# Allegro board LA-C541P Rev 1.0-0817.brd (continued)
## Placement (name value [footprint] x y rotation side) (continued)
PD704  SDMK0340L-7-F_SOD323-2~D  [SDMK0340L-7-F_SOD323-2]  34.78 37.29 90 top
PD1001  PDS5100H-13_POWERDI5-3~D  [PDS5100H-13_POWERDI5-3]  123.04 135.17 0 bottom
PD1002  PDS5100H-13_POWERDI5-3~D  [PDS5100H-13_POWERDI5-3]  291.05 14.73 270 top
PD1010  BAT54CW-7-F SOT-323  [BAT54CW_SOT323-3]  341.26 54.97 90 top
PD1100  -  [SDMK0340L-7-F_SOD323-2]  338.99 58.95 0 top
PD1101  SDMK0340L-7-F_SOD323-2~D  [SDMK0340L-7-F_SOD323-2]  266.42 40.29 90 bottom
PD1102  -  [SDMK0340L-7-F_SOD323-2]  323.83 46.95 270 top
PD1103  -  [SDMK0340L-7-F_SOD323-2]  322.13 46.95 270 top
PH1100  100K_0402_1%_TSM0B104F4251RZ  [R_0402]  225.96 69.49 0 bottom
PH1101  220K_0402_5%_ERTJ0EV224J  [R_0402]  234.12 67.33 180 bottom
PH1102  220K_0402_5%_ERTJ0EV224J  [R_0402]  221.26 17.23 0 top
PH1103  220K_0402_5%_ERTJ0EV224J  [R_0402]  242.06 66.97 180 bottom
PH1104  220K_0402_5%_ERTJ0EV224J  [R_0402]  235.86 17.8 180 top
PH1600  100K_0402_1%_TSM0B104F4251RZ  [R_0402]  259.64 18.83 0 top
PH1601  100K_0402_1%_TSM0B104F4251RZ  [R_0402]  261.81 22.58 90 top
PJP1  JUMP_1x3m  [JUMP_43X118]  45.47 33.61 90 top
PJP2  PAD-OPEN1x1m  [JUMP_43X39]  197.26 129.88 0 bottom
PJP3  -  [JUMP_43X79]  35.08 15.67 180 top
PJP4  PAD-OPEN1x1m  [JUMP_43X39]  34.62 18.74 180 top
PJP5  -  [JUMP_43X79]  31.65 16.78 180 top
PJP6  PAD-OPEN1x1m  [JUMP_43X39]  193.86 99.46 180 top
PJP7  PAD-OPEN1x3m  [JUMP_43X118]  196.32 99.56 0 top
PJP8  -  [JUMP_43X79]  121.34 102.84 270 bottom
PJP9  -  [JUMP_43X79]  14.79 41.7 0 top
PJP10  -  [JUMP_43X79]  221.67 126.31 270 top
PJP11  -  [JUMP_43X79]  224.29 118.36 180 top
PJP12  PAD-OPEN1x1m  [JUMP_43X39]  188.68 114.83 180 bottom
PJP13  PAD-OPEN1x1m  [JUMP_43X39]  192.59 102.92 90 bottom
PJP14  PAD-OPEN1x1m  [JUMP_43X39]  287.71 30.88 0 top
PJP15  -  [JUMP_43X79]  150.47 127.88 270 top
PJP16  -  [JUMP_43X79]  179.73 99.21 0 top
PJP17  PAD-OPEN 4x4m  [JUMP_43X118]  222.79 98.85 270 top
PJP18  PAD-OPEN 4x4m  [JUMP_43X118]  228.05 98.85 270 top
PJP19  -  [JUMP_43X79]  150.63 118.94 180 top
PJP20  -  [JUMP_43X79]  210.67 98.95 270 top
PJP21  -  [JUMP_43X79]  214.33 93.57 180 top
PJP22  PAD-OPEN 4x4m  [JUMP_43X118]  304.88 25.9 90 top
PJP23  -  [JUMP_43X79]  304.86 33.98 180 top
PJP24  -  [JUMP_43X79]  245.8 79.6 180 top
PJP25  -  [JUMP_43X79]  323.73 29 90 top
PJP26  -  [JUMP_43X79]  119.8 140 90 bottom
PJP100  PAD-OPEN 43x118  [JUMP_43X118]  342.35 5.59 270 top
PJP101  PAD-OPEN 43x118  [JUMP_43X118]  347.69 5.59 270 top
PJP102  PAD-OPEN 43x118  [JUMP_43X118]  346.1 49.25 90 bottom
PJP103  PAD-OPEN 43x118  [JUMP_43X118]  340.7 49.25 90 bottom
PJP200  PAD-OPEN 1x2m~D  [JUMP_43X79]  78.46 13.44 90 bottom
PJP201  PAD-OPEN1x1m  [JUMP_43X39]  64.68 15.7 180 bottom
PJP202  PAD-OPEN1x1m  [JUMP_43X39]  63.92 13.42 180 bottom
PJP203  JUMP_1x3m  [JUMP_43X118]  74.17 31.71 180 bottom
PJP204  JUMP_1x3m  [JUMP_43X118]  74.51 37.04 180 bottom
PJP300  PAD-OPEN 43x118  [JUMP_43X118]  317.95 17.61 180 top
PJP301  PAD-OPEN 1x2m~D  [JUMP_43X79]  334.14 17.48 180 top
PJP400  -  [JUMP_43X79]  12.42 56.68 0 top
PJP401  -  [JUMP_43X79]  22.87 61.21 90 top
PJP500  -  [JUMP_43X79]  81.68 10.33 0 top
PJP700  PAD-OPEN1x1m  [JUMP_43X39]  270.41 34.42 90 bottom
PJP800  PAD-OPEN 1x2m~D  [JUMP_43X79]  102.09 114.45 90 top
PJP801  PAD-OPEN 43x118  [JUMP_43X118]  101.32 114.57 270 bottom
PJP900  PAD-OPEN1x1m  [JUMP_43X39]  231.18 91.54 270 bottom
PJP901  PAD-OPEN1x1m  [JUMP_43X39]  232.37 81.77 270 bottom
PJP1100  PAD-OPEN1x1m  [JUMP_43X39]  260.07 47.9 180 bottom
PJP1800  -  [JUMP_43X79]  63.65 8.28 0 top
PJPDC1  ACES_50493-0110N-001  [ACES_50493-0110N-001_11P]  31.11 55.66 0 bottom
PL1  SMB3025500YA_2P  [CHENG_SMB3025500YA_2P]  236.15 78.7 180 top
PL2  FBMJ4516HS720NT_2P  [TAIYO_FBMJ4516HS720NT_2P]  266.6 7.96 180 top
PL3  BLM15BX102SN1D_2P  [MURAT_BLM15HG601SN1D_2P]  14.96 20.93 270 top
PL4  SMB3025500YA_2P  [CHENG_SMB3025500YA_2P]  46.11 50.11 180 bottom
PL5  SMB3025500YA_2P  [CHENG_SMB3025500YA_2P]  46.11 46.6 180 bottom
PL6  FBMJ4516HS720NT_2P  [TAIYO_FBMJ4516HS720NT_2P]  266.6 10.31 180 top
PL100  1UH_6.6A_20%_5X5X3_M  [L_5X5X3_M_2P]  338.19 14.28 90 top
PL101  2.2UH_7.8A_20%  [PANAS_ETQP3W2R2WFN_2P]  346.04 13.7 270 top
PL102  3.3UH_PIMB104T-3R3MS_10A_20%  [TOKO_FDVE1040-H-3R3M-P3_2P]  343.87 35.5 90 bottom
PL201  1UH_11A_20%_7X7X3_M  [L_7X7X3_M_2P]  69.96 26.67 270 top
PL301  1UH_6.6A_20%_5X5X3_M  [L_5X5X3_M_2P]  325.61 17.61 180 top
PL400  1UH_2.8A_30%_4X4X2_F  [L_4X4X2_F_2P]  21.38 55.71 90 top
PL500  HCB1608KF-121T30_0603  [TAI-T_HCB1608KF-121T3_L0603_2P]  68.06 10.61 0 top
PL501  1UH_1277AS-H-1R0N-P2_3.3A_30%  [MAG_MLV-FY12N1R0M-O1L_2P]  76.53 8.97 0 top
PL700  1UH_6.6A_20%_5X5X3_M  [L_5X5X3_M_2P]  296.4 15.78 270 top
PL701  3.3UH_6.5A_20%_7X7X3_M  [L_7X7X3_M_2P]  279.36 25.82 270 top
PL800  1UH_6.6A_20%_5X5X3_M  [L_5X5X3_M_2P]  95.74 124.78 270 bottom
PL1100  HCB2012KF-121T50_0805  [TAI-T_HCB2012KF-121T50_2P]  238.15 8.6 270 top
PL1101  HCB2012KF-121T50_0805  [TAI-T_HCB2012KF-121T50_2P]  239.86 8.59 270 top
PL1200  0.15UH_PCME064T-R15MS_36A_20%  [CYNTE_PCME064T-R15MS_4P]  234.59 62.89 180 bottom
PL1201  0.15UH_PCME064T-R15MS_36A_20%  [CYNTE_PCME064T-R15MS_4P]  234.59 52.73 180 bottom
PL1202  0.15UH_PCME064T-R15MS_36A_20%  [CYNTE_PCME064T-R15MS_4P]  234.59 42.57 180 bottom
PL1400  0.15UH_PCME064T-R15MS_36A_20%  [CYNTE_PCME064T-R15MS_4P]  228.63 12.97 180 top
PL1401  0.15UH_PCME064T-R15MS_36A_20%  [CYNTE_PCME064T-R15MS_4P]  228.63 23.13 180 top
PL1402  0.15UH_PCME064T-R15MS_36A_20%  [CYNTE_PCME064T-R15MS_4P]  228.63 33.29 180 top
PL1600  0.47UH_MMD05CZR47M_12A_20%  [MAG_MMD05CZR47M_4P]  255.76 22.7 270 top
PL1700  0.47UH_MMD05CZR47M_12A_20%  [MAG_MMD05CZR47M_4P]  228.21 73.02 180 bottom
PL1800  HCB1608KF-121T30_0603  [TAI-T_HCB1608KF-121T3_L0603_2P]  50.33 11.42 270 top
PL1801  1UH_1277AS-H-1R0N-P2_3.3A_30%  [MAG_MLV-FY12N1R0M-O1L_2P]  59.3 8.53 0 top
PQ1  AO3409_SOT23  [NTR4502PT1G_SOT23-3]  249.48 10.82 90 top
PQ2  FDV301N_G_NL_SOT23-3~D  [FDV301N_NL_SOT23-3]  12.68 23.47 90 top
PQ3  -  [MMST3904-7-F_SOT323-3]  11.14 28.01 270 top
PQ5  SI7149DP  [SI7447DP_SO8_5P]  38.84 50.95 270 bottom
PQ8  DCX124EK-7-F_SC74R-6  [IMD2AT-108_SC74-6]  14.95 25.29 180 top
PQ100  -  [SIS412DN-T1-GE3_POWERPAK8-5]  340.74 21.57 90 top
PQ101  -  [SIS412DN-T1-GE3_POWERPAK8-5]  347.85 39.94 180 top
PQ102  -  [FDMC7692S_MLP8-5]  344.49 25.27 180 top
PQ103  -  [FDMC7692S_MLP8-5]  349.76 38.31 0 top
PQ201  -  [SIR472DP-T1-GE3_POWERPAK8-5]  67.72 22.31 0 bottom
PQ202  SIRA06DP-T1_POWERPAK-SO8-5  [SIR472DP-T1-GE3_POWERPAK8-5]  74.77 27.83 270 bottom
PQ700  DMP3056L-7 1P SOT23-3  [NTR4502PT1G_SOT23-3]  40.35 34.72 0 bottom
PQ701  SI7149DP  [SI7447DP_SO8_5P]  41.96 38.12 180 bottom
PQ702  DMP3056L-7 1P SOT23-3  [NTR4502PT1G_SOT23-3]  44.35 34.72 0 bottom
PQ703  DMP3056L-7 1P SOT23-3  [NTR4502PT1G_SOT23-3]  35.98 29.05 180 bottom
PQ704  -  [SIR472DP-T1-GE3_POWERPAK8-5]  284.06 27.93 270 top
PQ705  -  [FDMC7692S_MLP8-5]  286.6 20.36 90 top
PQ706  DMP3056L-7 1P SOT23-3  [NTR4502PT1G_SOT23-3]  32 31.86 0 bottom
PQ707  -  [DMN66D0LDW-7_SOT363-6]  269.05 24.28 270 top
PQ708  -  [DMN65D8LDW-7_SOT363-6]  30.96 37.71 0 top
PQ800  -  [SIS412DN-T1-GE3_POWERPAK8-5]  99.78 120.82 270 top
PQ801  -  [SI7716ADN-T1-GE3_POWERPAK8-5]  96.12 118.31 0 top
PQ1001  SI7149DP  [SI7447DP_SO8_5P]  127.23 138.45 90 bottom
PQ1002  -  [SI4835DDY-T1-E3_SO8]  261.92 16.15 270 top
PQ1003  SI7149DP  [SI7447DP_SO8_5P]  259.87 13.48 180 top
PQ1004  SI7149DP  [SI7447DP_SO8_5P]  287.7 15.07 180 top
PQ1005  -  [DMN65D8LDW-7_SOT363-6]  269.79 39.69 90 bottom
PQ1011  SSM3K7002FU_SC70-3~D  [SSM3K7002FU_SC70-3]  342.12 61.11 90 top
PQ1072  AO3409_SOT23  [NTR4502PT1G_SOT23-3]  345.97 53.87 0 top
PQ1073  -  [DMN65D8LDW-7_SOT363-6]  27.73 37.1 90 top
PQ1074  -  [DMN65D8LDW-7_SOT363-6]  338.32 43.46 90 top
PR1  1K_0402_5%  [R_0402]  48.49 27.96 180 bottom
PR2  100K_0402_5%  [R_0402]  250.15 7.44 90 top
PR3  100_0804_8P4R_5%  [RP_0804_8P4R]  252.09 7.13 90 top
PR7  0_0402_5%  [R_0402]  12.55 20.93 180 top
PR8  2.2K_0402_5%  [R_0402]  9.75 19.98 0 top
PR9  33_0402_5%  [R_0402]  10.71 20.93 180 top
PR10  100K_0402_1%  [R_0402]  13.82 20.04 90 top
PR11  10K_0402_1%  [R_0402]  11.49 25.99 180 top
PR12  15K_0402_1%  [R_0402]  14.71 19.09 180 top
PR13  10K_0402_5%  [R_0402]  9.86 27.55 180 top
PR16  1M_0402_5%  [R_0402]  45.93 44.19 270 bottom
PR18  100K_0402_5%  [R_0402]  30.91 45.44 270 bottom
PR19  4.7K_0805_5%  [R_0805]  47.45 44.17 270 bottom
PR20  10K_0402_5%  [R_0402]  43.52 43.25 270 bottom
PR22  1M_0402_5%  [R_0402]  45.24 41.85 0 bottom
PR33  0_0402_5%  [R0402_0OHM]  249.21 13.29 180 top
PR100  6.49K_0402_1%  [R_0402]  345.83 30.44 0 top
PR101  15K_0402_1%  [R_0402]  348.59 33.29 0 bottom
PR102  10K_0402_1%  [R_0402]  349.54 31.07 180 bottom
PR103  0_0402_5%  [R0402_0OHM]  344.89 32.29 270 top
PR104  10K_0402_1%  [R_0402]  348.63 32.34 0 bottom
PR105  22.1K_0402_1%  [R_0402]  345.83 29.55 0 top
PR106  22.1K_0402_1%  [R_0402]  347.18 33.18 270 top
PR107  100K_0402_1%  [R_0402]  346.68 30.56 180 bottom
PR108  0_0402_5%  [R0402_0OHM]  345.77 31.45 0 bottom
PR109  2.2_0603_5%  [R_0603]  351.52 34.16 90 top
PR110  2.2_0603_5%  [R_0603]  352.13 26.56 90 top
PR111  4.7_1206_5%  [R_1206]  346.42 22.5 90 top
PR112  4.7_1206_5%  [R_1206]  353.66 41.17 270 top
PR113  0_0402_5%  [R_0402]  346.51 27.45 0 top
PR114  200_0402_1%  [R_0402]  350.83 33.29 270 bottom
PR200  2.2_0603_5%  [R_0603]  64.16 17.42 180 bottom
PR201  5.11K_0402_1%  [R_0402]  60.16 21.37 270 bottom
PR202  4.7_1206_5%  [R_1206]  66.7 18.88 180 top
PR203  5.1_0603_5%  [R_0603]  55.33 21.61 270 bottom
PR204  12K_0402_1%  [R_0402]  56.16 16.1 270 top
PR205  1M_0402_1%  [R_0402]  55.45 17.93 0 bottom
PR206  200K_0402_5%  [R_0402]  55.45 17.04 0 bottom
PR207  20K_0402_1%  [R_0402]  57.67 16.97 0 top
PR208  100K_0402_5%  [R_0402]  55.45 16.15 0 bottom
PR209  100K_0402_1%  [R_0402]  55.4 19.2 0 bottom
PR210  2.2_0603_5%  [R_0603]  59.21 22.18 180 bottom
PR303  1M_0402_1%  [R_0402]  328.35 21.61 180 top
PR305  4.7_1206_5%  [R_1206]  324 13.55 0 top
PR306  0_0402_5%  [R_0402]  329.91 21.62 270 top
PR307  36.5K_0402_1%  [R_0402]  332.05 23.58 0 top
PR308  0_0402_5%  [R0402_0OHM]  331.04 21.61 0 top
PR309  1K_0402_5%  [R_0402]  332.97 22.69 180 top
PR310  62K_0402_1%  [R_0402]  331.18 22.68 90 top
PR311  10_0402_1%  [R_0402]  333.86 24.53 180 top
PR312  0_0603_5%  [R_0603]  325.15 22.5 270 top
PR314  0_0402_5%  [R0402_0OHM]  332.08 24.53 180 top
PR315  100K_0402_1%  [R_0402]  330.11 22.5 180 top
PR316  0_0402_5%  [R0402_0OHM]  332.08 25.42 180 top
PR400  100K_0402_5%  [R_0402]  13.19 60.35 0 top
PR401  0_0402_5%  [R0402_0OHM]  18.21 59.47 180 top
PR402  1M_0402_5%  [R_0402]  18.21 58.58 180 top
PR403  4.7_0603_5%  [R_0603]  18.17 53.56 180 top
PR404  36.5K_0402_1%  [R_0402]  15.96 60.43 180 top
PR405  11.5K_0402_1%  [R_0402]  15.05 58.66 0 top
PR500  100K_0402_1%  [R_0402]  76.13 5.46 270 top
PR501  0_0402_5%  [R_0402]  77.06 5.47 270 top
PR502  100K_0402_5%  [R_0402]  77.33 6.9 180 top
PR503  2.2_0603_5%  [R_0603]  74.54 12.03 90 top
PR504  4.7_1206_5%  [R_1206]  77.47 11.38 90 top
PR505  100_0402_1%  [R_0402]  70.34 12.94 270 top
PR506  0_0402_5%  [R_0402]  71.26 12.95 270 top
PR507  0_0402_5%  [R_0402]  75.19 5.47 270 top
PR508  0_0402_5%  [R_0402]  72.22 12.93 270 top
PR509  100K_0402_1%  [R_0402]  69.38 12.04 90 top
PR510  1M_0402_1%  [R_0402]  74.29 5.48 270 top
PR511  10K_0402_1%  [R_0402]  70.53 5.49 270 top
PR512  10K_0402_1%  [R_0402]  72.43 4.6 90 top
PR513  10K_0402_1%  [R_0402]  69.59 4.57 90 top
PR514  10K_0402_1%  [R_0402]  71.49 5.5 270 top
PR700  0_0402_5%  [R_0402]  335.11 49.12 270 top
PR701  0.005_1206_1%  [R_1206_4P-D]  43.52 40.15 0 bottom
PR703  0_0402_5%  [R_0402]  37.55 33.01 180 bottom
PR704  100_0402_1%  [R_0402]  42.71 30.75 180 bottom
PR706  4.12K_0603_1%  [R_0603]  275.75 37.97 270 top
PR709  100K_0402_1%  [R_0402]  35.81 27.26 180 bottom
PR710  0_0402_5%  [R0402_0OHM]  41.81 29.5 270 bottom
PR711  0_0402_5%  [R0402_0OHM]  42.7 29.5 270 bottom
PR712  100K_0402_1%  [R_0402]  34.03 27.26 180 bottom
PR713  12.1_0402_1%  [R_0402]  33.56 33.93 0 bottom
PR714  0_0402_5%  [R0402_0OHM]  31.34 27.26 0 bottom
PR715  20_0402_1%  [R_0402]  34.47 32.91 180 bottom
PR716  0_0402_5%  [R0402_0OHM]  269.92 38.39 270 top
PR717  10_1206_5%  [R_1206]  282.39 41.98 180 top
PR718  49.9K_0402_1%  [R_0402]  272.58 37.6 90 top
PR719  294K_0402_1%  [R_0402]  272.6 36.72 180 top
PR720  121K_0402_1%  [R_0402]  274.73 37.43 180 top
PR721  0_0402_5%  [R0402_0OHM]  274.73 36.54 180 top
PR722  100K_0402_1%  [R_0402]  273.81 38.31 0 top
PR723  0.01_1206_1%  [R_1206_4P-D]  274.75 18.37 180 top
PR724  4.7_1206_5%  [R_1206]  283.93 18.28 0 top
PR725  0_0402_5%  [R_0402]  268.49 33.42 0 top
PR726  0_0402_5%  [R0402_0OHM]  268.49 35.2 0 top
PR727  0_0402_5%  [R0402_0OHM]  268.49 32.53 0 top
PR728  0_0402_5%  [R0402_0OHM]  270.92 28.07 90 top
PR729  0_0402_5%  [R0402_0OHM]  268.49 31.64 0 top
PR730  0_0402_5%  [R_0402]  268.49 34.31 0 top
PR737  665K_0402_1%  [R_0402]  267.6 30.75 0 top
PR738  3M_0402_5%  [R_0402]  269.39 30.77 270 top
PR740  10K_0402_1%  [R_0402]  269.46 28.9 270 top
PR743  0_0402_5%  [R0402_0OHM]  268.52 27.2 180 top
PR744  45.3K_0402_1%  [R_0402]  267.61 34.27 180 top
PR745  100K_0402_1%  [R_0402]  268.52 28.98 180 top
PR757  10K_0402_5%  [R_0402]  271.81 28.99 270 top
PR758  20K_0402_1%  [R_0402]  270.21 25.3 180 top
PR760  5.36K_0402_1%  [R_0402]  271.04 25.3 0 top
PR761  10_0402_1%  [R_0402]  275.12 27.12 90 top
PR762  10_0402_1%  [R_0402]  274.17 27.12 90 top
PR764  2.74K_0402_1%  [R_0402]  271.91 24.45 270 top
PR765  2.2_0603_5%  [R_0603]  277.28 32.75 0 top
PR766  0_0402_5%  [R_0402]  32.49 36.66 0 top
PR767  1M_0402_5%  [R_0402]  31.54 36.66 180 top
PR768  1M_0402_5%  [R_0402]  33.38 39.71 270 top
PR769  1M_0402_5%  [R_0402]  31.67 40.6 180 top
PR770  1M_0402_5%  [R_0402]  29.57 38.56 270 top
PR771  0_0402_5%  [R_0402]  26.78 39.64 0 top
PR772  100K_0402_1%  [R_0402]  26.78 40.6 0 top
PR773  0_0402_5%  [R_0402]  24.93 40.6 0 top
PR800  100K_0402_5%  [R_0402]  102.24 130.6 90 top
PR801  2.2_0603_5%  [R_0603]  103.74 125.05 270 top
PR802  107K_0402_1%  [R_0402]  102.98 128.59 180 bottom
PR804  0_0402_5%  [R_0402]  99.01 129.42 0 bottom
PR805  4.7_1206_5%  [R_1206]  93.96 121.1 270 top
PR806  470K_0402_1%  [R_0402]  98.47 129.84 90 top
PR807  5.11K_0402_1%  [R_0402]  99.44 130.48 90 top
PR808  12K_0402_1%  [R_0402]  100.37 129.84 90 top
PR809  0_0402_5%  [R_0402]  99.01 128.54 0 bottom
PR900  0_0402_5%  [R0402_0OHM]  236.82 91.23 270 bottom
PR901  47K_0402_5%  [R_0402]  234.92 90.34 90 bottom
PR902  12.7K_0402_1%  [R_0402]  234.09 82.02 0 bottom
PR903  10K_0402_1%  [R_0402]  235.93 82.04 0 bottom
PR1001  330K_0402_5%  [R_0402]  326.73 53.56 270 top
PR1002  0_0402_5%  [R_0402]  126.62 143.63 180 bottom
PR1003  330K_0402_5%  [R_0402]  282.46 5.02 0 top
PR1004  0_0402_5%  [R0402_0OHM]  251.94 14.43 180 top
PR1005  1K_1206_5%  [R_1206]  282.73 6.54 0 top
PR1006  0_0402_5%  [R0402_0OHM]  328.24 54.44 0 top
PR1007  100_0603_1%  [R_0603]  327.69 53.36 0 top
PR1008  100_0603_1%  [R_0603]  327.69 55.96 0 top
PR1009  0_0402_5%  [R0402_0OHM]  336.45 59.34 270 top
PR1010  100_0603_1%  [R_0603]  327.69 52.15 0 top
PR1011  47_0805_5%  [R_0805]  326.97 49.42 0 top
PR1012  0_0402_5%  [R0402_0OHM]  330.67 58.43 90 top
PR1013  100K_0402_5%  [R_0402]  332.96 46.38 90 top
PR1014  0_0402_5%  [R0402_0OHM]  332.45 58.43 90 top
PR1015  100_0603_1%  [R_0603]  334.04 47.65 90 top
PR1016  0_0402_5%  [R0402_0OHM]  331.56 58.43 90 top
PR1017  0_0402_5%  [R0402_0OHM]  332.96 48.2 90 top
PR1018  1M_0402_5%  [R_0402]  334.21 60.22 0 top
PR1019  0_0402_5%  [R0402_0OHM]  333.34 58.43 90 top
PR1020  0_0402_5%  [R0402_0OHM]  334.23 58.43 90 top
PR1021  0_0402_5%  [R0402_0OHM]  336 48.2 90 top
PR1022  0_0402_5%  [R0402_0OHM]  336.89 48.2 90 top
PR1023  0_0402_5%  [R0402_0OHM]  335.11 58.43 90 top
PR1024  0_0402_5%  [R0402_0OHM]  337.34 58.43 90 top
PR1025  0_0402_5%  [R0402_0OHM]  338.34 57.17 0 top
PR1026  100_0603_1%  [R_0603]  326 50.92 0 top
PR1027  0_0402_5%  [R0402_0OHM]  338.34 55.39 0 top
PR1028  1M_0402_5%  [R_0402]  338.34 56.28 0 top
PR1029  100_0603_1%  [R_0603]  338.42 54 0 top
PR1030  10K_0402_5%  [R_0402]  341.86 57.61 180 top
PR1031  330K_0402_5%  [R_0402]  342.1 53.22 180 top
PR1032  0_0402_5%  [R0402_0OHM]  341.77 56.73 0 top
PR1033  0_0402_5%  [R_0402]  268.84 41.22 90 bottom
PR1034  1M_0402_5%  [R_0402]  270.63 42.12 180 bottom
PR1035  1M_0402_5%  [R_0402]  270.5 38.37 180 bottom
PR1036  1M_0402_5%  [R_0402]  271.64 37.23 180 bottom
PR1037  1M_0402_5%  [R_0402]  269.87 37.23 180 bottom
PR1099  100K_0402_5%  [R_0402]  347.49 57.65 180 top
PR1100  100_0402_1%  [R_0402]  201.48 55.84 180 top
PR1101  12K_0402_1%  [R_0402]  265.32 44.86 90 top
PR1102  7.5K_0603_1%  [R_0603]  264.19 46.33 270 top
PR1103  499_0402_1%  [R_0402]  265.21 39.83 180 top
PR1104  45.3_0402_1%  [R_0402]  265.21 42.69 180 top
PR1105  100_0402_1%  [R_0402]  264.3 40.79 0 top
PR1106  0_0402_5%  [R0402_0OHM]  261.52 54.42 0 top
PR1107  0_0402_5%  [R0402_0OHM]  264.19 52.1 270 top
PR1108  0_0402_5%  [R0402_0OHM]  261.52 53.53 0 top
PR1109  1K_0402_1%  [R_0402]  263.3 52.1 270 top
PR1110  100_0402_1%  [R_0402]  262.14 39.83 0 top
PR1111  100_0402_1%  [R_0402]  201.48 56.79 180 top
PR1112  30K_0402_1%  [R_0402]  259.47 46.31 0 bottom
PR1113  10_0402_1%  [R_0402]  262.14 40.79 0 top
PR1114  10K_0402_1%  [R_0402]  263.12 44.66 180 top
PR1115  0_0402_5%  [R0402_0OHM]  263.05 41.74 180 top
PR1116  14.3K_0402_1%  [R_0402]  263.12 48.22 180 top
PR1117  49.9_0402_1%  [R_0402]  262.14 42.69 0 top
PR1118  1.5K_0402_1%  [R_0402]  264.52 49.99 180 top
PR1119  100_0402_1%  [R_0402]  217.86 42.37 180 bottom
PR1120  34.8K_0402_1%  [R_0402]  260.39 44.53 180 bottom
PR1121  0_0402_5%  [R0402_0OHM]  259.22 51.33 0 bottom
PR1122  0_0402_5%  [R0402_0OHM]  258.28 53.16 90 bottom
PR1123  1K_0402_1%  [R_0402]  259.22 54.06 0 bottom
PR1124  100_0402_1%  [R_0402]  200.56 44.41 0 top
PR1125  100_0402_1%  [R_0402]  217.86 43.33 180 bottom
PR1126  0_0402_5%  [R0402_0OHM]  261.58 37.63 270 top
PR1127  1K_0402_1%  [R_0402]  260.69 39.4 270 top
PR1128  0_0402_5%  [R0402_0OHM]  259.79 36.72 0 top
PR1129  100_0402_1%  [R_0402]  200.56 45.36 0 top
PR1130  49.9_0402_1%  [R_0402]  259.74 51.25 90 top
PR1131  1K_0402_1%  [R_0402]  259.73 50.38 0 top
PR1132  25.5K_0402_1%  [R_0402]  257.07 48.01 90 bottom
PR1133  3.65K_0402_1%  [R_0402]  257.96 50.36 90 top
PR1134  49.9_0402_1%  [R_0402]  258.91 38.51 270 top
PR1135  24.9K_0402_1%  [R_0402]  258.72 41.47 90 bottom
PR1136  1K_0402_1%  [R_0402]  258.01 39.39 0 top
PR1137  3.65K_0402_1%  [R_0402]  258.04 35.83 180 top
PR1138  12.7K_0402_1%  [R_0402]  257.07 51.28 270 top
PR1139  16.2K_0402_1%  [R_0402]  256.26 38.5 180 top
PR1140  75K_0402_1%  [R_0402]  257.09 53.04 180 top
PR1141  75K_0402_1%  [R_0402]  255.35 37.61 0 top
PR1142  165K_0402_1%  [R_0402]  256.2 52.15 180 top
PR1143  93.1K_0402_1%  [R_0402]  250.54 53.17 90 top
PR1144  165K_0402_1%  [R_0402]  256.26 35.83 180 top
PR1145  107K_0402_1%  [R_0402]  252.58 36.09 180 top
PR1146  93.1K_0402_1%  [R_0402]  251.44 53.18 90 top
PR1147  107K_0402_1%  [R_0402]  252.58 37.1 180 top
PR1148  93.1K_0402_1%  [R_0402]  252.87 53.72 0 top
PR1149  107K_0402_1%  [R_0402]  252.58 38.12 180 top
PR1150  1K_0402_1%  [R_0402]  250.46 47.26 0 top
PR1151  2.2_0603_5%  [R_0603]  249.9 46.18 0 top
PR1152  75K_0402_1%  [R_0402]  254.27 43.01 0 bottom
PR1153  24.9K_0402_1%  [R_0402]  254.27 42.12 0 bottom
PR1154  2.26K_0402_1%  [R_0402]  252.37 51.28 270 bottom
PR1155  52.3K_0402_1%  [R_0402]  254.27 47.45 0 bottom
PR1156  3.92K_0402_1%  [R_0402]  254.27 46.57 0 bottom
PR1157  24.9K_0402_1%  [R_0402]  254.27 45.68 0 bottom
PR1158  97.6K_0402_1%  [R_0402]  254.27 44.79 0 bottom
PR1159  97.6K_0402_1%  [R_0402]  254.27 43.9 0 bottom
PR1160  2.26K_0402_1%  [R_0402]  252.13 41.55 180 bottom
PR1161  2.26K_0402_1%  [R_0402]  253.26 51.28 270 bottom
PR1162  2.26K_0402_1%  [R_0402]  252.13 40.53 180 bottom
PR1163  2.26K_0402_1%  [R_0402]  254.15 51.28 270 bottom
PR1164  2.26K_0402_1%  [R_0402]  252.13 39.52 180 bottom
PR1165  0_0402_5%  [R0402_0OHM]  251.37 48.15 180 top
PR1166  0_0402_5%  [R0402_0OHM]  251.24 42.69 180 bottom
PR1167  61.9K_0402_1%  [R_0402]  249.59 48.15 180 top
PR1168  61.9K_0402_1%  [R_0402]  251.24 43.64 180 bottom
PR1169  1K_0402_1%  [R_0402]  251.49 51.28 270 top
PR1170  1K_0402_1%  [R_0402]  250.32 42.44 0 top
PR1198  0_0402_5%  [R0402_0OHM]  262.14 43.64 0 top
PR1199  45.3_0402_1%  [R_0402]  265.21 41.74 180 top
PR1200  2_0603_5%  [R_0603]  234.53 58.4 0 bottom
PR1201  2_0603_5%  [R_0603]  244.39 60.03 180 bottom
PR1202  2_0603_5%  [R_0603]  244.26 49.87 180 bottom
PR1203  2_0603_5%  [R_0603]  234.58 48.24 0 bottom
PR1204  10_0402_1%  [R_0402]  229.12 67.14 0 bottom
PR1205  10_0402_1%  [R_0402]  229.12 56.98 0 bottom
PR1206  2_1206_5%  [R_1206]  236.72 67.36 0 bottom
PR1207  2_1206_5%  [R_1206]  237.13 57.12 0 bottom
PR1208  2_0603_5%  [R_0603]  244.31 39.43 180 bottom
PR1209  2_0603_5%  [R_0603]  235.9 36.79 90 bottom
PR1210  10_0402_1%  [R_0402]  229.12 46.82 0 bottom
PR1211  2_1206_5%  [R_1206]  236.73 46.65 0 bottom
PR1400  2_0603_5%  [R_0603]  228.56 17.43 0 top
PR1401  2_0603_5%  [R_0603]  238.42 15.83 180 top
PR1402  2_0603_5%  [R_0603]  238.39 26.25 180 top
PR1403  2_0603_5%  [R_0603]  228.56 27.64 0 top
PR1404  10_0402_1%  [R_0402]  223.11 17.23 0 top
PR1405  10_0402_1%  [R_0402]  223.15 27.39 0 top
PR1406  2_1206_5%  [R_1206]  230.66 8.33 0 top
PR1407  2_1206_5%  [R_1206]  230.69 19.04 0 top
PR1408  2_0603_5%  [R_0603]  238.37 36.15 180 top
PR1409  2_0603_5%  [R_0603]  228.59 37.8 0 top
PR1410  10_0402_1%  [R_0402]  223.15 37.55 0 top
PR1411  2_1206_5%  [R_1206]  230.59 29.23 0 top
PR1600  27K_0402_1%  [R_0402]  261.8 30.2 180 top
PR1601  8.25K_0402_1%  [R_0402]  264.07 28.26 90 top
PR1602  15K_0402_1%  [R_0402]  261.4 28.33 90 top
PR1603  2_0603_5%  [R_0603]  261.93 33.56 270 top
PR1604  6.19K_0402_1%  [R_0402]  264.98 27.72 0 top
PR1605  1.5K_0402_1%  [R_0402]  264.4 25.01 0 top
PR1606  10K_0402_1%  [R_0402]  259.9 24 180 top
PR1607  100_0402_1%  [R_0402]  259.61 32.14 90 top
PR1608  10_0402_1%  [R_0402]  258.72 33.05 270 top
PR1609  0_0402_5%  [R_0402]  257.84 33.05 270 top
PR1610  150K_0402_1%  [R_0402]  261.14 26.12 0 top
PR1611  49.9_0402_1%  [R_0402]  256.95 33.05 270 top
PR1612  10K_0402_1%  [R_0402]  260.03 22.93 270 top
PR1613  0_0402_5%  [R_0402]  262.04 24.34 180 top
PR1614  2_1206_5%  [R_1206]  250.53 22.75 90 top
PR1615  2_0603_5%  [R_0603]  255.65 32.04 90 top
PR1616  61.9K_0402_1%  [R_0402]  260.92 23.47 270 top
PR1617  1K_0402_1%  [R_0402]  263.84 23.53 180 top
PR1618  866_0402_1%  [R_0402]  263.78 21.75 180 top
PR1619  866_0402_1%  [R_0402]  263.78 20.86 180 top
PR1620  100_0402_1%  [R_0402]  203.59 43.23 0 top
PR1621  100_0402_1%  [R_0402]  203.2 44.44 0 top
PR1700  2_0603_5%  [R_0603]  228.24 68.24 0 bottom
PR1701  2_0603_5%  [R_0603]  238.02 69.74 180 bottom
PR1702  2_1206_5%  [R_1206]  229.26 78.32 0 bottom
PR1800  100K_0402_1%  [R_0402]  59.29 5.3 270 top
PR1801  0_0402_5%  [R_0402]  60.24 5.3 270 top
PR1802  100K_0402_5%  [R_0402]  60.12 6.51 180 top
PR1803  2.2_0603_5%  [R_0603]  56.81 11.77 90 top
PR1804  4.7_1206_5%  [R_1206]  59.69 10.75 90 top
PR1805  100_0402_1%  [R_0402]  52.47 12.69 270 top
PR1806  0_0402_5%  [R_0402]  53.46 12.56 270 top
PR1807  0_0402_5%  [R_0402]  56.43 5.3 270 top
PR1808  0_0402_5%  [R_0402]  54.5 12.59 270 top
PR1809  1M_0402_1%  [R_0402]  57.38 5.3 270 top
PR1810  100K_0402_1%  [R_0402]  51.45 12.69 270 top
PR1811  10K_0402_1%  [R_0402]  53.57 5.3 270 top
PR1812  10K_0402_1%  [R_0402]  54.53 4.39 90 top
PR1813  10K_0402_1%  [R_0402]  52.62 4.39 90 top
PR1814  10K_0402_1%  [R_0402]  55.48 5.3 270 top
PR1815  0_0402_5%  [R_0402]  51.67 5.3 270 top
PT1  PAD~D  [TPC12]  201.4 106.7 0 top
PU1  -  [TS5A63157DCKR_SC70-6]  9.97 18.63 270 top
PU101  -  [TPS51285BRUKR_QFN20_3X3]  349.19 31.94 270 top
PU105  TC7SH08FU_SSOP5~D  [TC7SH08FU_SSOP5]  336.96 40.06 0 top
PU200  -  [RT8207MZQW_WQFN20_3X3]  60.58 15.87 180 bottom
PU300  -  [SYX198DQNC_QFN10_3X3]  328.66 19.02 0 top
PU400  -  [SY8003DFC_DFN8_2X2]  15.61 56.73 270 top
PU500  -  [NB681GD-Z_QFN13_2X3]  73.07 9.19 0 top
PU700  BQ24780S  [BQ24780RUYR_WQFN28_4X4]  274.28 34.71 270 top
PU800  -  [TPS51212DSCR_SON10_3X3]  101.84 128.29 180 top
PU900  -  [AP7175SP-13_SO-8EP-8]  236.5 83.55 180 bottom
PU1001  CD3301BRHHR  [CD3301RHHR_QFN36_6X6]  331.7 50.79 0 top
PU1100  -  [NCP81205MNTXG_QFN52_6X6]  259.35 48.24 270 top
PU1200  -  [NCP81382MNTXG_QFN39_4X6]  240.47 59.4 90 bottom
PU1201  -  [NCP81382MNTXG_QFN39_4X6]  240.47 49.11 90 bottom
PU1202  -  [NCP81382MNTXG_QFN39_4X6]  240.52 38.7 90 bottom
PU1400  -  [NCP81382MNTXG_QFN39_4X6]  234.5 16.46 270 top
PU1401  -  [NCP81382MNTXG_QFN39_4X6]  234.5 27 270 top
PU1402  -  [NCP81382MNTXG_QFN39_4X6]  234.48 37.19 270 top
PU1600  NCP81210MNTWG_QFN40_5x5  [NCP81210MNTWG_QFN40_5X5]  258.82 30.51 270 top
PU1700  -  [NCP81382MNTXG_QFN39_4X6]  234.13 68.99 90 bottom
PU1800  -  [NB681GD-Z_QFN13_2X3]  55.95 9.03 0 top
PWRSW1  @SHORT PADS~D  [SHORTPADS]  209.08 152.61 90 bottom
Q4  -  [DMN65D8LW-7_SOT323-3]  164.04 67.2 180 top
Q5  -  [DMN65D8LW-7_SOT323-3]  201.38 78.37 90 bottom
Q14  -  [MMBT3904WT1G_SC70-3]  107.67 34.63 90 top
Q15  -  [MMBT3904WT1G_SC70-3]  332.53 22.82 180 bottom
Q16  -  [MMBT3904WT1G_SC70-3]  179.34 44.37 90 bottom
Q17  -  [MMBT3904WT1G_SC70-3]  29.49 25.11 270 bottom
Q21  -  [DMP3050LVT-7_TSOT26-6]  110.29 138.55 270 bottom
Q22  -  [DMN65D8LW-7_SOT323-3]  111.93 134.26 270 bottom
Q24  -  [LP2301ALT1G_SOT23-3]  100.49 133.19 0 bottom
Q26  -  [MMBT3904WT1G_SC70-3]  241.32 69.63 270 bottom
Q27  -  [MMBT3904WT1G_SC70-3]  210.47 102.3 0 top
Q28  -  [MMBT3904WT1G_SC70-3]  198.61 99.23 90 bottom
Q29  -  [DMN66D0LDW-7_SOT363-6]  9.38 43.04 270 top
Q74  -  [DMN66D0LDW-7_SOT363-6]  304.19 8.1 270 top
Q86  -  [DDTA114EUA-7-F_SOT323-3]  308.88 7.51 90 top
Q87  -  [DMN65D8LW-7_SOT323-3]  226.8 110.7 180 top
Q186  -  [AO4435L_SO8]  230.21 106.55 180 top
Q295  -  [DMN66D0LDW-7_SOT363-6]  210.86 75.2 180 top
Q325  -  [DMN66D0LDW-7_SOT363-6]  240.35 117.52 0 top
Q327  -  [DMN65D8LW-7_SOT323-3]  229.91 124.23 270 top
Q343  -  [DMN66D0LDW-7_SOT363-6]  167.24 138.97 270 bottom
Q347  -  [DMN66D0LDW-7_SOT363-6]  171 132.67 180 bottom
Q353  -  [DMN66D0LDW-7_SOT363-6]  152.57 123.99 270 bottom
Q355  -  [DMN66D0LDW-7_SOT363-6]  149.58 114.08 0 bottom
Q359  -  [DMN65D8LW-7_SOT323-3]  302.67 11.92 0 top
Q364  -  [DMN66D0LDW-7_SOT363-6]  146.52 120.1 0 bottom
Q365  -  [DMN66D0LDW-7_SOT363-6]  170.02 141.88 0 bottom
Q366  -  [DMN66D0LDW-7_SOT363-6]  243.11 103.15 0 top
Q367  -  [DMN66D0LDW-7_SOT363-6]  168.87 95.53 0 top
Q369  -  [DMN66D0LDW-7_SOT363-6]  171.41 95.53 0 top
Q370  -  [DMN65D8LW-7_SOT323-3]  195.2 98.41 315 bottom
QE2  -  [DMN66D0LDW-7_SOT363-6]  213.51 104.28 90 bottom
QH3  -  [DMN65D8LW-7_SOT323-3]  111.93 131.66 270 bottom
QH4  -  [DMN66D0LDW-7_SOT363-6]  109.17 128.62 180 top
QH5  -  [DMN65D8LW-7_SOT323-3]  112.7 130.12 0 top
QN5  -  [DMN65D8LW-7_SOT323-3]  20.28 26.82 270 top
QV1  -  [DMN65D8LW-7_SOT323-3]  157.65 138.45 270 bottom
QZ2  -  [LP2301ALT1G_SOT23-3]  194.69 124.19 0 top
R1  4.7K_0402_5%  [R_0402]  210.37 72.16 180 top
R2  4.7K_0402_5%  [R_0402]  211.92 74.36 90 top
R3  4.3K_0402_5%  [R_0402]  165.76 76.73 0 top
R4  10K_0402_5%  [R_0402]  208.43 76.58 90 top
R5  4.3K_0402_5%  [R_0402]  165.76 77.62 0 top
R7  0_0402_5%  [R0402_0OHM]  170.58 126.72 0 bottom
R8  33_0402_5%  [R_0402]  170.58 125.76 0 bottom
R9  33_0402_5%  [R_0402]  170.58 124.81 0 bottom
R10  10K_0402_5%  [R_0402]  162.04 65.88 90 top
R11  10K_0402_5%  [R_0402]  174.81 69.93 180 top
R12  0_0402_5%  [R_0402]  238.89 86.96 90 top
R13  0_0402_5%  [R_0402]  240.25 93.39 270 top
R19  0_0402_5%  [R_0402]  174.08 76.35 0 top
R21  0_0402_5%  [R_0402]  257.56 93.87 90 top
R22  0_0402_5%  [R_0402]  257.55 88.29 180 top
R23  0_0402_5%  [R_0402]  240.77 95.16 270 top
R24  0_0402_5%  [R_0402]  240.97 91.59 180 top
R25  0_0402_5%  [R_0402]  256.66 91.94 0 top
R26  0_0402_5%  [R_0402]  256.65 93.87 90 top
R27  0_0402_5%  [R_0402]  257.55 90.2 180 top
R28  0_0402_5%  [R_0402]  257.55 89.3 180 top
R29  0_0402_5%  [R_0402]  239.68 92.29 0 bottom
R30  0_0402_5%  [R_0402]  239.74 93.37 0 bottom
R37  100K_0402_5%  [R_0402]  214.1 75.95 90 top
R38  0_0402_5%  [R_0402]  242.02 102.13 90 top
R39  0_0402_5%  [R_0402]  246.49 104.24 90 top
R40  0_0402_5%  [R_0402]  241.15 102.89 90 top
R41  0_0402_5%  [R_0402]  245.77 103.04 0 top
R42  100K_0402_5%  [R_0402]  119.36 142.95 90 bottom
R43  0_0402_5%  [R_0402]  193.15 112.51 180 bottom
R51  100K_0402_5%  [R_0402]  175.23 74.55 0 top
R60  100K_0402_5%  [R_0402]  144.09 77.49 0 top
R63  0_0603_5%  [R0603_0OHM]  229.89 110.16 90 top
R64  0_0603_5%  [R0603_0OHM]  231.29 110.16 90 top
R65  0_0603_5%  [R0603_0OHM]  232.06 112.52 90 top
R66  0_0603_5%  [R0603_0OHM]  233.44 112.52 90 top
R67  0_0603_5%  [R0603_0OHM]  234.07 110.11 90 top
R68  0_0603_5%  [R0603_0OHM]  235.46 110.11 90 top
R69  0_0603_5%  [R0603_0OHM]  236.31 112.49 90 top
R70  0_0603_5%  [R0603_0OHM]  237.71 112.49 90 top
R71  10K_0402_5%  [R_0402]  163.36 68.42 270 bottom
R72  0_0402_5%  [R0402_0OHM]  164.27 66.63 180 bottom
R96  4.99K_0402_1%  [R_0402]  174.82 138.07 90 top
R97  4.99K_0402_1%  [R_0402]  148.55 95.94 180 top
R98  4.7K_0402_5%  [R_0402]  177.5 138.97 180 top
R99  4.7K_0402_5%  [R_0402]  184.46 137.39 0 bottom
R100  4.7K_0402_5%  [R_0402]  145.98 142 180 top
R101  4.99K_0402_1%  [R_0402]  143.3 141.09 90 top
R102  4.7K_0402_5%  [R_0402]  148.52 97.75 180 top
R103  4.7K_0402_5%  [R_0402]  118.83 147.57 0 bottom
R104  4.7K_0402_5%  [R_0402]  148.26 108.67 180 top
R105  4.7K_0402_5%  [R_0402]  169.06 91.97 0 top
R106  4.99K_0402_1%  [R_0402]  171.74 92.87 270 top
R107  4.7K_0402_5%  [R_0402]  162.1 93.52 180 bottom
R109  4.7K_0402_5%  [R_0402]  155.35 136.16 0 bottom
R115  4.7K_0402_5%  [R_0402]  177.5 138.08 180 top
R116  4.7K_0402_5%  [R_0402]  185.03 137.98 270 top
R117  4.7K_0402_5%  [R_0402]  184.46 134.53 0 bottom
R118  4.7K_0402_5%  [R_0402]  184.46 135.48 0 bottom
R119  4.7K_0402_5%  [R_0402]  184.46 138.34 0 bottom
R120  4.7K_0402_5%  [R_0402]  184.43 140.6 0 bottom
R121  4.7K_0402_5%  [R_0402]  186.02 138.87 0 top
R122  4.7K_0402_5%  [R_0402]  184.5 140.29 0 top
R123  4.7K_0402_5%  [R_0402]  185.03 136.22 270 top
R124  4.7K_0402_5%  [R_0402]  184.46 136.43 0 bottom
R125  4.7K_0402_5%  [R_0402]  147.32 105.67 90 top
R126  4.7K_0402_5%  [R_0402]  146.44 105.67 90 top
R127  4.7K_0402_5%  [R_0402]  155.35 138.2 0 bottom
R128  4.7K_0402_5%  [R_0402]  149.39 97.76 270 top
R129  4.7K_0402_5%  [R_0402]  168.21 137.07 0 bottom
R130  560_0402_1%  [R_0402]  311.18 8.35 270 top
R131  560_0402_1%  [R_0402]  310.22 8.35 270 top
R132  4.7K_0402_5%  [R_0402]  168.21 136.18 0 bottom
R133  4.7K_0402_5%  [R_0402]  155.35 139.21 0 bottom
R134  4.7K_0402_5%  [R_0402]  208.88 108.66 180 bottom
R135  100K_0402_5%  [R_0402]  163.36 65.76 270 bottom
R136  4.7K_0402_5%  [R_0402]  145.98 141.11 180 top
R137  4.7K_0402_5%  [R_0402]  153.87 140.95 180 top
R138  4.7K_0402_5%  [R_0402]  153.87 141.91 180 top
R139  4.7K_0402_5%  [R_0402]  153.87 139.05 180 top
R140  4.7K_0402_5%  [R_0402]  155.35 133.12 0 bottom
R141  4.7K_0402_5%  [R_0402]  153.87 140 180 top
R142  4.7K_0402_5%  [R_0402]  155.35 134.13 0 bottom
R143  4.7K_0402_5%  [R_0402]  155.35 135.15 0 bottom
R146  4.7K_0402_5%  [R_0402]  148.21 105.67 90 top
R147  4.7K_0402_5%  [R_0402]  144.61 105.89 90 top
R148  4.7K_0402_5%  [R_0402]  150.88 105.67 90 top
R149  4.7K_0402_5%  [R_0402]  153.55 105.67 90 top
R150  4.7K_0402_5%  [R_0402]  149.99 106.37 180 top
R151  4.7K_0402_5%  [R_0402]  152.66 106.43 90 top
R152  4.7K_0402_5%  [R_0402]  151.77 105.67 90 top
R153  4.7K_0402_5%  [R_0402]  162.1 92.57 180 bottom
R154  4.7K_0402_5%  [R_0402]  162.1 91.61 180 bottom
R155  4.7K_0402_5%  [R_0402]  169.06 92.86 0 top
R156  4.7K_0402_5%  [R_0402]  162.1 92.61 180 top
R157  4.7K_0402_5%  [R_0402]  162.1 91.65 180 top
R158  4.7K_0402_5%  [R_0402]  162.1 94.51 180 top
R159  4.7K_0402_5%  [R_0402]  162.1 96.42 180 bottom
R160  4.7K_0402_5%  [R_0402]  162.1 93.56 180 top
R161  4.7K_0402_5%  [R_0402]  162.1 95.46 180 bottom
R162  4.7K_0402_5%  [R_0402]  162.1 94.47 180 bottom
R208  0_0603_5%  [R0603_0OHM]  110.76 150.47 0 bottom
R209  0_0603_1%  [R0603_0OHM]  254.36 116.16 90 top
R213  0_0603_5%  [R_0603]  269.4 41.69 135 top
R222  100K_0402_5%  [R_0402]  120.81 146.65 180 bottom
R317  20K_0402_5%  [R_0402]  9.17 53.12 0 top
R336  100K_0402_5%  [R_0402]  112.79 156.53 180 bottom
R339  100K_0402_5%  [R_0402]  112.79 155.64 180 bottom
R360  0_0402_5%  [R_0402]  25.43 11.58 90 top
R361  0_0402_5%  [R_0402]  239.65 90.67 0 top
R362  0_0402_5%  [R_0402]  252.65 85.31 270 top
R363  10K_0402_5%  [R_0402]  20.01 28.6 0 top
R370  33_0402_5%  [R_0402]  290.05 33.37 270 top
R371  560_0402_5%  [R_0402]  254.99 85.31 270 top
R372  0_0402_5%  [R0402_0OHM]  19.15 28.6 180 top
R373  2.2K_0402_5%  [R_0402]  250.82 85.48 0 top
R374  43K_0402_1%  [R_0402]  127.23 128.79 45 top
R375  1K_0402_5%  [R_0402]  248.17 83.71 270 top
R376  20K_0402_5%  [R_0402]  249.07 84.59 180 top
R377  1M_0402_5%  [R_0402]  240.86 120.5 0 top
R378  1M_0402_5%  [R_0402]  226.8 122.5 90 top
R379  10K_0402_5%  [R_0402]  180.05 118.26 0 bottom
R381  100K_0402_5%  [R_0402]  97.64 92.21 90 top
R382  10K_0402_5%  [R_0402]  142.12 133.56 180 top
R383  10K_0402_5%  [R_0402]  299.43 5.4 0 top
R384  10K_0402_5%  [R_0402]  299.5 4.31 0 top
R385  10K_0402_5%  [R_0402]  303.75 4.63 90 top
R386  0_0402_5%  [R_0402]  9.92 36.35 90 top
R387  10K_0402_5%  [R_0402]  298.75 6.67 180 top
R388  0_0402_5%  [R0402_0OHM]  49 31.19 0 top
R389  0_0402_5%  [R_0402]  299.08 8.15 90 top
R396  8.2K_0402_5%  [R_0402]  200.64 97.52 180 bottom
R399  2.2K_0402_5%  [R_0402]  202.99 98.75 90 bottom
R400  33_0402_5%  [R_0402]  290.05 34.23 90 top
R403  10K_0402_5%  [R_0402]  270.55 41.48 45 top
R405  10K_0402_5%  [R_0402]  237.06 87.83 0 top
R407  10K_0402_5%  [R_0402]  256.63 87.33 0 top
R408  10K_0402_5%  [R_0402]  237.06 88.74 0 top
R409  10K_0402_5%  [R_0402]  256.62 92.98 0 top
R410  10K_0402_5%  [R_0402]  257.52 96.59 180 top
R411  10K_0402_5%  [R_0402]  257.52 97.48 180 top
R413  10K_0402_5%  [R_0402]  239.7 89.78 0 top
R414  10K_0402_5%  [R_0402]  249.93 82.68 0 top
R415  100K_0402_5%  [R_0402]  335.2 42.9 270 bottom
R416  100K_0402_5%  [R_0402]  335.2 41.12 270 bottom
R417  0_0402_5%  [R_0402]  190.73 106.81 90 bottom
R418  0_0402_5%  [R_0402]  128.95 127.9 90 top
R422  100K_0402_5%  [R_0402]  107.46 133.35 0 bottom
R423  47K_0402_5%  [R_0402]  109.24 133.35 0 bottom
R425  1.33K_0402_1%  [R_0402]  207.88 99.16 270 bottom
R426  100K_0402_5%  [R_0402]  142.14 134.45 180 top
R427  0_0402_5%  [R_0402]  104.06 132.98 90 bottom
R428  0_0402_5%  [R_0402]  103.04 132.98 90 bottom
R429  0_0402_5%  [R_0402]  116.95 140.3 270 bottom
R430  0_0402_5%  [R_0402]  116.06 140.3 270 bottom
R432  47K_0402_5%  [R_0402]  208.9 113.19 180 bottom
R435  0_0402_5%  [R_0402]  197.39 97.68 0 bottom
R492  1M_0402_5%  [R_0402]  159.2 147.6 180 top
R501  10K_0402_5%  [R_0402]  4.75 48.98 180 top
R502  10K_0402_5%  [R_0402]  5.68 48.98 0 top
R503  100K_0402_5%  [R_0402]  9.31 44.27 90 top
R504  100K_0402_5%  [R_0402]  5.43 41.06 0 top
R506  100K_0402_5%  [R_0402]  10.22 40.66 180 top
R513  100K_0402_5%  [R_0402]  10.44 44.15 0 top
R519  100K_0402_5%  [R_0402]  157.15 76.86 180 top
R545  10K_0402_5%  [R_0402]  252.53 103.9 90 top
R546  10K_0402_5%  [R_0402]  253.99 103.9 90 top
R549  10K_0402_5%  [R_0402]  257.1 116.61 180 top
R553  4.7K_0402_5%  [R_0402]  255.83 120.8 180 top
R554  4.7K_0402_5%  [R_0402]  256.98 113.44 180 top
R555  0_0402_5%  [R0402_0OHM]  257.1 118.38 180 top
R556  0_0402_5%  [R0402_0OHM]  256.85 114.38 180 top
R557  10K_0402_5%  [R_0402]  256.19 117.5 0 top
R558  0_0402_5%  [R0402_0OHM]  254.92 119.91 0 top
R559  4.7K_0402_5%  [R_0402]  255.93 115.4 0 top
R561  1K_0402_1%  [R_0402]  251.07 104.81 270 top
R562  3.01K_0402_1%  [R_0402]  245.8 115.34 180 top
R571  75_0402_1%  [R_0402]  250.17 138.44 90 top
R572  75_0402_1%  [R_0402]  242.55 138.44 90 top
R573  75_0402_1%  [R_0402]  248.9 138.44 90 top
R574  75_0402_1%  [R_0402]  241.34 138.44 90 top
R720  100K_0402_5%  [R_0402]  321.72 34.82 270 top
R721  100K_0402_5%  [R_0402]  167.73 133.05 0 bottom
R722  100K_0402_5%  [R_0402]  167.73 134.01 0 bottom
R723  100K_0402_5%  [R_0402]  217.89 122.59 270 top
R755  10K_0402_5%  [R_0402]  190.99 143.91 0 bottom
R756  33_0402_5%  [R_0402]  188.69 147.53 90 top
R757  100K_0402_5%  [R_0402]  166.52 148.43 270 top
R758  100K_0402_5%  [R_0402]  147.65 77.49 0 top
R759  10K_0402_5%  [R_0402]  180.29 115.3 180 top
R763  10K_0402_5%  [R_0402]  170.65 106.89 0 bottom
R773  10K_0402_5%  [R_0402]  181.25 106.18 180 top
R775  10K_0402_5%  [R_0402]  176.66 105.21 90 top
R779  10K_0402_5%  [R_0402]  182.13 106.09 270 top
R782  100K_0402_5%  [R_0402]  171.57 107.78 180 bottom
R783  100K_0402_5%  [R_0402]  187.62 112.29 0 top
R795  10_0402_1%  [R_0402]  186.14 106.85 180 top
R797  0_0402_5%  [R0402_0OHM]  210.34 115.06 270 bottom
R800  100K_0402_5%  [R_0402]  170.65 111.28 0 bottom
R802  0_0402_5%  [R0402_0OHM]  192.24 106.67 0 bottom
R803  100K_0402_5%  [R_0402]  171.57 110.4 180 bottom
R804  1K_0402_1%  [R_0402]  182.9 115.28 90 top
R805  100K_0402_5%  [R_0402]  174.82 105.64 90 top
R807  10_0402_1%  [R_0402]  173.91 107.45 90 top
R810  100K_0402_5%  [R_0402]  208.88 119.51 270 bottom
R811  10K_0402_5%  [R_0402]  209.77 119.51 270 bottom
R814  100K_0402_5%  [R_0402]  192.11 111.27 0 bottom
R817  100K_0402_5%  [R_0402]  205.92 103.91 180 top
R819  100K_0402_5%  [R_0402]  208.9 120.38 180 bottom
R820  0_0402_5%  [R_0402]  216.06 123.47 0 top
R822  2.2K_0402_5%  [R_0402]  192.23 115.17 0 bottom
R825  10K_0402_5%  [R_0402]  207.98 121.27 0 bottom
R829  2.2K_0402_5%  [R_0402]  192.23 114.29 0 bottom
R834  0_0402_5%  [R0402_0OHM]  203.16 102.58 90 bottom
R835  10K_0402_5%  [R_0402]  196.31 123.25 270 bottom
R836  100_0402_1%  [R_0402]  191.79 119.56 0 bottom
R837  10K_0402_5%  [R_0402]  208.9 112.3 180 bottom
R838  2.2K_0402_5%  [R_0402]  208.9 114.16 180 bottom
R840  0_0402_5%  [R0402_0OHM]  216.06 122.58 0 top
R841  2.2K_0402_5%  [R_0402]  208.9 115.05 180 bottom
R843  8.2K_0402_5%  [R_0402]  192.18 109.43 0 bottom
R845  0_0402_5%  [R0402_0OHM]  198.27 118.67 0 bottom
R847  10K_0402_5%  [R_0402]  181.63 93.82 90 bottom
R848  10K_0402_5%  [R_0402]  179.85 93.82 90 bottom
R849  10K_0402_5%  [R_0402]  178.96 93.82 90 bottom
R850  100K_0402_5%  [R_0402]  180.74 93.82 90 bottom
R858  10K_0402_5%  [R_0402]  187.02 92.36 90 bottom
R859  10K_0402_5%  [R_0402]  184.99 92.3 90 bottom
R860  10K_0402_5%  [R_0402]  184.1 92.3 90 bottom
R861  10K_0402_5%  [R_0402]  182.52 93.82 90 bottom
R862  0_0402_5%  [R_0402]  177.37 102.46 180 bottom
R863  0_0402_5%  [R_0402]  177.37 101.57 180 bottom
R864  49.9_0402_1%  [R_0402]  187.91 92.36 90 bottom
R866  0_0402_5%  [R0402_0OHM]  196.5 118.65 90 bottom
R869  10K_0402_5%  [R_0402]  187.86 116.99 90 top
R870  100K_0402_5%  [R_0402]  206.19 119.35 90 bottom
R872  10K_0402_5%  [R_0402]  204.12 123.63 270 bottom
R874  1K_0402_5%  [R_0402]  200.88 122.72 90 bottom
R875  62K_0402_5%  [R_0402]  208.9 111.42 180 bottom
R876  100K_0402_5%  [R_0402]  201.77 122.72 90 bottom
R877  0_0402_5%  [R_0402]  154.87 122.19 180 top
R878  0_0402_5%  [R0402_0OHM]  154.79 125.25 270 top
R879  10K_0402_5%  [R_0402]  203.23 123.63 270 bottom
R880  100K_0402_5%  [R_0402]  207.08 119.35 90 bottom
R881  0_0402_5%  [R0402_0OHM]  307.93 30.5 180 top
R885  10_0402_1%  [R_0402]  197.14 103.76 270 bottom
R892  10K_0402_5%  [R_0402]  192.23 113.4 0 bottom
R895  33_0402_5%  [R_0402]  179.28 125.95 0 bottom
R897  33_0402_5%  [R_0402]  187.42 120.67 0 bottom
R899  33_0402_5%  [R_0402]  176.69 118.89 0 bottom
R900  33_0402_5%  [R_0402]  187.42 119.65 0 bottom
R901  33_0402_5%  [R_0402]  178.54 119.86 270 bottom
R932  10K_0402_5%  [R_0402]  300.25 7.25 90 top
R935  100K_0402_5%  [R_0402]  219.43 91.33 180 top
R936  0_0402_5%  [R_0402]  179.28 126.91 0 bottom
R940  100K_0402_5%  [R_0402]  225.07 103.83 90 top
R943  1K_0402_5%  [R_0402]  308.52 5.8 180 top
R944  20K_0402_5%  [R_0402]  225.08 106.57 180 top
R953  33_0402_5%  [R_0402]  194.49 118.65 90 bottom
R955  1K_0402_5%  [R_0402]  304.44 10.57 270 top
R956  430_0402_5%  [R_0402]  300.89 11.06 90 top
R1068  0_0402_5%  [R0402_0OHM]  203.61 118.59 90 bottom
R1069  1K_0402_5%  [R_0402]  198.01 103.74 0 bottom
R1137  10K_0402_5%  [R_0402]  110.83 151.53 90 bottom
R1138  100K_0402_5%  [R_0402]  111.74 151.52 90 bottom
R1144  0_0402_5%  [R0402_0OHM]  251.34 115.18 180 top
R1167  150_0402_5%  [R_0402]  250.8 144.48 180 top
R1170  150_0402_5%  [R_0402]  250.8 145.37 180 top
R1171  150_0402_5%  [R_0402]  228.69 146.44 90 top
R1970  0_0402_5%  [R0402_0OHM]  209.28 90.64 270 top
R1971  0_0402_5%  [R0402_0OHM]  208.39 90.64 270 top
R1972  0_0402_5%  [R0402_0OHM]  213.22 76.86 180 top
R1977  10K_0402_5%  [R_0402]  209.38 76.58 90 top
R1978  10K_0402_5%  [R_0402]  163.49 76.46 90 bottom
R1981  100K_0402_5%  [R_0402]  192.7 120.45 180 bottom
R1985  0_0402_5%  [R0402_0OHM]  207.99 119.51 270 bottom
R2158  100K_0402_5%  [R_0402]  187.82 106.26 180 bottom
R2160  100K_0402_5%  [R_0402]  167.73 155.46 90 top
R2164  33_0402_5%  [R_0402]  157.11 145.5 0 top
R2165  33_0402_5%  [R_0402]  157.11 144.61 0 top
R2166  33_0402_5%  [R_0402]  160.93 147.52 90 top
R2167  33_0402_5%  [R_0402]  161.82 147.52 90 top
R2168  33_0402_5%  [R_0402]  162.71 147.52 90 top
R2169  33_0402_5%  [R_0402]  163.6 147.52 90 top
R2170  33_0402_5%  [R_0402]  164.49 147.52 90 top
R2171  33_0402_5%  [R_0402]  165.38 147.52 90 top
R2172  33_0402_5%  [R_0402]  159.28 156.37 270 top
R2173  33_0402_5%  [R_0402]  160.17 156.37 270 top
R2174  33_0402_5%  [R_0402]  161.06 156.37 270 top
R2175  33_0402_5%  [R_0402]  161.95 156.37 270 top
R2176  33_0402_5%  [R_0402]  162.84 156.37 270 top
R2177  33_0402_5%  [R_0402]  163.73 156.37 270 top
R2178  33_0402_5%  [R_0402]  164.68 153.83 270 top
R2179  33_0402_5%  [R_0402]  165.57 153.83 270 top
R2189  100K_0402_5%  [R_0402]  146.52 122.7 0 bottom
R2194  4.7K_0402_5%  [R_0402]  150.26 110.76 180 bottom
R2195  4.7K_0402_5%  [R_0402]  168.75 139.78 0 top
R2196  4.7K_0402_5%  [R_0402]  170.91 142.32 0 top
R2197  100K_0402_5%  [R_0402]  148.77 122.6 0 bottom
R2198  4.7K_0402_5%  [R_0402]  149.76 115.53 0 bottom
R3664  1K_0402_5%  [R_0402]  170.58 123.86 0 bottom
R3665  1K_0402_5%  [R_0402]  179.28 124.05 0 bottom
R3666  1K_0402_5%  [R_0402]  179.28 123.1 0 bottom
R3667  33_0402_5%  [R_0402]  179.28 125 0 bottom
R3668  1K_0402_5%  [R_0402]  170.58 122.91 0 bottom
R3669  33_0402_5%  [R_0402]  171.49 121.95 180 bottom
R3670  33_0402_5%  [R_0402]  180.19 122.14 180 bottom
R3722  1M_0402_5%  [R_0402]  151.36 143.76 90 top
R3727  100K_0402_5%  [R_0402]  125.25 145.51 270 bottom
R3728  1K_0402_5%  [R_0402]  201.39 144.13 270 bottom
R3730  100K_0402_5%  [R_0402]  210.34 113.21 270 bottom
R3736  4.7K_0402_5%  [R_0402]  149.81 121.31 270 bottom
R3737  4.7K_0402_5%  [R_0402]  145.98 115.36 90 bottom
R3738  4.7K_0402_5%  [R_0402]  246.69 102.13 180 top
R3739  4.7K_0402_5%  [R_0402]  244.21 102.13 180 top
R3740  100K_0402_5%  [R_0402]  171.57 112.24 180 bottom
R3741  100K_0402_5%  [R_0402]  173.77 110.38 0 top
R3744  100K_0402_5%  [R_0402]  170.92 99.59 180 top
R3745  4.7K_0402_5%  [R_0402]  172.19 94.3 0 top
R3746  100K_0402_5%  [R_0402]  169.96 100.48 0 top
R3747  4.7K_0402_5%  [R_0402]  172.65 98.39 0 top
R3748  10K_0402_5%  [R_0402]  170.84 104.99 0 bottom
R3750  100K_0402_5%  [R_0402]  172.11 76.09 0 top
R3752  33_0402_5%  [R_0402]  293.93 41.54 270 top
R3753  100K_0402_5%  [R_0402]  35.89 22.65 270 top
R3754  33K_0402_5%  [R_0402]  205.91 109.89 90 top
R3755  33_0402_5%  [R_0402]  187.42 121.62 0 bottom
R3757  10_0402_1%  [R_0402]  206.66 132.35 0 bottom
R3758  33_0402_5%  [R_0402]  294.87 41.54 270 top
RC1  24.9_0402_1%  [R_0402]  203.18 66.01 270 top
RC2  24.9_0402_1%  [R_0402]  167.1 62.44 0 top
RC5  2.2K_0402_5%  [R_0402]  152.25 17.17 180 top
RC6  2.2K_0402_5%  [R_0402]  160.5 13.99 180 top
RC66  20_0402_5%  [R_0402]  189.65 71.32 90 bottom
RC74  10K_0402_5%  [R_0402]  120.77 130.67 270 top
RC75  10K_0402_5%  [R_0402]  105.61 115.8 180 top
RC76  10K_0402_5%  [R_0402]  105.61 116.69 180 top
RC79  10K_0402_5%  [R_0402]  112.5 120.8 0 bottom
RC121  1K_0402_5%  [R_0402]  145.96 13.79 90 top
RC122  0_0402_5%  [R_0402]  146.89 13.79 90 top
RC124  1K_0402_5%  [R_0402]  155.98 14.96 270 top
RC126  1K_0402_5%  [R_0402]  152.04 13.8 90 top
RC127  1K_0402_5%  [R_0402]  164.32 13.79 90 top
RC128  0_0402_5%  [R_0402]  160.57 125.13 270 top
RC129  0_0402_5%  [R_0402]  151.35 19.59 270 top
RC132  150_0402_5%  [R_0402]  161.52 14.29 90 top
RC133  1.5K_0402_5%  [R_0402]  159.68 125.13 270 top
RC135  51_0402_5%  [R_0402]  169.71 6.69 180 top
RC138  51_0402_5%  [R_0402]  147.8 13.79 90 top
RC143  0_0402_5%  [R_0402]  163.43 13.79 90 top
RC144  0_0402_5%  [R_0402]  160.5 14.94 180 top
RC154  0_0402_5%  [R0402_0OHM]  191.7 102.36 180 top
RC155  56.2_0402_1%  [R_0402]  195.64 5.53 0 top
RC156  220_0402_5%  [R_0402]  197.39 5.53 0 top
RC157  100_0402_5%  [R_0402]  195.64 6.45 0 top
RC158  499_0402_1%  [R_0402]  195.52 9.65 90 top
RC159  60.4_0402_1%  [R_0402]  156.81 68.04 270 top
RC164  1K_0402_5%  [R_0402]  157.75 68.04 270 top
RC166  1K_0402_5%  [R_0402]  163.43 15.56 90 top
RC167  30_0402_5%  [R_0402]  197.56 9.65 90 top
RC168  20_0402_5%  [R_0402]  196.67 9.65 90 top
RC169  0_0402_5%  [R0402_0OHM]  214.58 73.38 270 top
RC171  0_0402_5%  [R_0402]  165.75 23.38 270 top
RC172  49.9_0402_1%  [R_0402]  198 16.41 270 top
RC173  100_0603_1%~D  [R_0603]  187.05 32.34 90 bottom
RC174  100_0603_1%  [R_0603]  183.65 14.87 90 top
RC175  100_0603_1%  [R_0603]  181.17 14.87 90 top
RC176  100_0603_1%  [R_0603]  183.65 13.41 270 top
RC177  30_0402_5%  [R_0402]  197.84 80.23 270 bottom
RC178  0_0402_5%  [R_0402]  189.51 69.09 90 bottom
RC179  0_0402_5%  [R_0402]  190.4 69.09 90 bottom
RC180  1K_0402_5%  [R_0402]  194.64 10.57 270 top
RC181  1K_0402_5%  [R_0402]  145.97 16.54 270 top
RC216  0_0603_1%  [R0603_0OHM]  153.5 17.29 270 top
RC217  0_0402_5%  [R_0402]  161.52 12.52 90 top
RC220  0_0402_5%  [R0402_0OHM]  179.24 51.95 90 bottom
RC221  49.9_0402_1%  [R_0402]  215.99 43.28 270 bottom
RC222  49.9_0402_1%  [R_0402]  188.68 21.3 270 bottom
RC223  0_0603_5%  [R_0603]  182.44 14.87 90 top
RC224  0_0603_5%  [R_0603]  182.44 13.41 270 top
RC226  100_0603_1%  [R_0603]  199.43 18.88 180 top
RC227  49.9_0402_1%  [R_0402]  197.05 15.49 90 top
RC228  49.9_0402_1%  [R_0402]  195.27 15.49 90 top
RC229  49.9_0402_1%  [R_0402]  196.16 15.49 90 top
RC230  100_0603_1%  [R_0603]  181.19 37.48 270 bottom
RC241  1.5K_0402_5%  [R_0402]  157.76 14.96 270 top
RC301  0_0402_5%  [R_0402]  200.37 143.21 90 bottom
RC302  0_0402_5%  [R_0402]  164.27 26.63 180 bottom
RC303  0_0402_5%  [R_0402]  189.29 96.79 180 top
RC304  0_0603_5%  [R0603_0OHM]  194.1 97.56 180 top
RC306  51_0402_5%  [R_0402]  162.54 14.83 270 top
RC307  0_0402_5%  [R0402_0OHM]  168.8 9.55 0 top
RC308  0_0402_5%  [R0402_0OHM]  168.8 8.66 0 top
RC309  0_0402_5%  [R0402_0OHM]  168.8 7.58 0 top
RC312  0_0402_5%  [R_0402]  169.71 5.67 180 top
RC313  0_0402_5%  [R_0402]  169.71 4.78 180 top
RC314  0_0402_5%  [R_0402]  149.67 13.79 90 top
RC315  0_0402_5%  [R_0402]  148.74 13.79 90 top
RC316  1.5K_0402_5%  [R_0402]  162.68 19.39 180 top
RC317  0_0402_5%  [R_0402]  193.86 5.53 0 top
RC318  47K_0402_5%  [R_0402]  189.74 102.48 180 top
RC319  0_0402_5%  [R0402_0OHM]  198.89 15.49 90 top
RC320  0_0402_5%  [R_0402]  204.56 101.37 0 top
RC321  1K_0402_5%  [R_0402]  173.97 10.04 90 top
RC322  1K_0402_5%  [R_0402]  172.98 10.03 90 top
RC323  1K_0402_5%  [R_0402]  172.09 10.03 90 top
RC324  1K_0402_5%  [R_0402]  176 10.04 90 top
RC325  1K_0402_5%  [R_0402]  174.98 10.04 90 top
RC326  1K_0402_5%  [R_0402]  216.03 73.49 0 top
RC327  0_0402_5%  [R_0402]  218.39 102.68 270 top
RC328  51_0402_5%  [R_0402]  135.3 121.95 225 bottom
RC329  0_0402_5%  [R_0402]  200.07 102.62 90 top
RC330  0_0402_5%  [R_0402]  89.26 24.61 270 top
RD3  1K_0402_5%  [R_0402]  103.79 48.15 0 top
RD4  1K_0402_5%  [R_0402]  103.79 49.93 0 top
RD5  1K_0402_5%  [R_0402]  107.24 48.41 180 top
RD6  0_0402_5%  [R0402_0OHM]  106.28 39.06 90 top
RD7  470_0402_1%  [R_0402]  103.92 39.14 0 top
RD8  0_0402_5%  [R_0402]  126.54 5.24 90 top
RD9  1K_0402_5%  [R_0402]  136.12 59.79 270 top
RD10  1K_0402_5%  [R_0402]  137.9 58.87 90 top
RD11  0_0402_5%  [R0402_0OHM]  107.39 53.24 90 top
RD12  1K_0402_5%  [R_0402]  103.79 49.04 0 top
RD13  0_0402_5%  [R_0402]  127.49 5.24 90 top
RD14  0_0402_5%  [R_0402]  107.37 55.01 180 top
RD15  0_0402_5%  [R0402_0OHM]  104.88 40.08 90 top
RD16  24.9_0402_1%  [R_0402]  138.71 54.38 0 top
RD17  0_0402_5%  [R0402_0OHM]  128.38 5.24 90 top
RD18  121_0402_1%  [R_0402]  167.1 63.46 0 top
RD19  0_0402_5%  [R_0402]  138.8 91.33 180 bottom
RD20  0_0402_5%  [R_0402]  129.37 90.71 270 bottom
RD21  75_0402_1%  [R_0402]  167.1 61.42 0 top
RD22  100_0402_1%  [R_0402]  167.1 60.41 0 top
RD23  2_0402_1%  [R_0402]  138.79 57.09 90 top
RD26  0_0402_5%  [R_0402]  128.42 90.71 270 bottom
RD27  0_0402_5%  [R_0402]  114.42 6.17 90 top
RD28  0_0402_5%  [R0402_0OHM]  126.55 7.03 180 top
RD29  0_0402_5%  [R0402_0OHM]  127.48 7.03 0 top
RD30  0_0402_5%  [R_0402]  129.33 6.16 270 top
RD31  0_0402_5%  [R0402_0OHM]  137.89 90.38 0 bottom
RD34  24.9_0402_1%  [R_0402]  137.44 7.08 270 top
RD35  0_0402_5%  [R0402_0OHM]  128.43 88.92 180 bottom
RD36  0_0402_5%  [R0402_0OHM]  129.36 88.92 0 bottom
RD37  0_0402_5%  [R0402_0OHM]  112.58 6.17 90 top
RD38  0_0402_5%  [R0402_0OHM]  113.53 6.17 90 top
RD39  0_0402_5%  [R0402_0OHM]  115.31 7.08 270 top
RD40  0_0402_5%  [R_0402]  113.52 7.96 0 top
RD41  2_0402_1%  [R_0402]  135.66 6.17 90 top
RD42  0_0402_5%  [R_0402]  112.59 7.96 180 top
RD43  1K_0402_5%  [R_0402]  131.2 7.07 0 top
